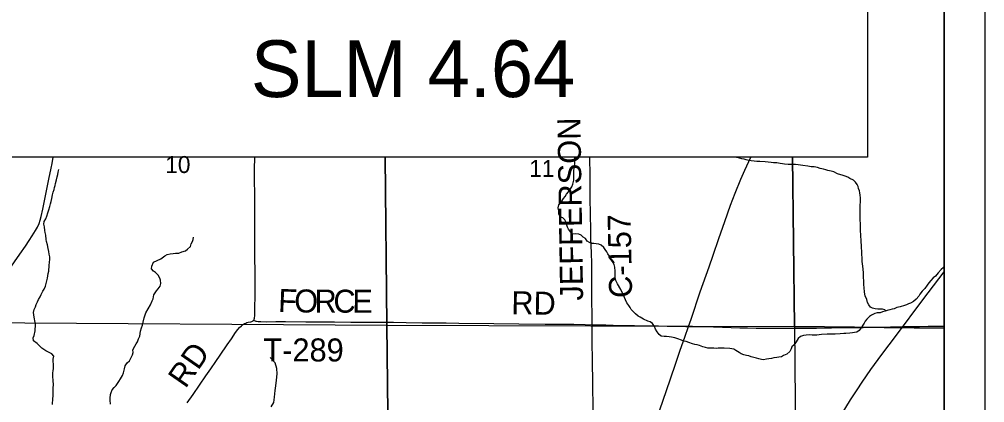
# Model space of a CAD drawing. Extents: x 0 to 34, y 0 to 22.
# Drawn here: x 6.615 to 9, y 16.212 to 17.158 of the extents above; entities that cross this region are included whole.
import ezdxf

# ---------------------------------------------------------------- set-up
doc = ezdxf.new("R2010")
doc.units = 0
for name, color, linetype in [('Default', 7, 'Continuous'), ('GM_X_County_Road', 7, 'Continuous'), ('GM_X_County_Road_Text', 7, 'Continuous'), ('GM_X_Minor_River', 7, 'Continuous'), ('GM_X_Rail_Line', 7, 'Continuous'), ('GM_X_Section', 7, 'Continuous'), ('GM_X_Section_Text', 7, 'Continuous'), ('GM_X_State_Route', 7, 'Continuous'), ('GM_X_Township_Road', 7, 'Continuous'), ('GM_X_Township_Road_Text', 7, 'Continuous'), ('SH_Cut_Line', 7, 'Continuous'), ('SH_Data', 7, 'Continuous'), ('SH_Text', 7, 'Continuous')]:
    doc.layers.add(name, color=color, linetype=linetype)

msp = doc.modelspace()

# ---------------------------------------------------------------- linework, layer by layer
at = {"layer": 'Default'}
msp.add_lwpolyline([(8.9, 14.3696), (8.9, 18.4271)], dxfattribs=at)
for points in [[(8.5252, 16.8178), (8.53, 16.4), (8.9, 16.3958), (8.9, 17.4137), (8.7107, 17.4109), (8.7107, 16.8178)], [(8.9, 15.3782), (8.9, 16.3958), (8.53, 16.4), (8.5395, 15.3753)]]:
    msp.add_lwpolyline(points, close=True, dxfattribs=at)
at = {"layer": 'GM_X_County_Road'}
for points in [[(6.5832, 16.5322), (6.5899, 16.541), (6.6165, 16.579), (6.6299, 16.5987), (6.639, 16.6124), (6.6465, 16.6236), (6.6552, 16.6371), (6.6597, 16.6454), (6.6636, 16.654), (6.6666, 16.6628), (6.669, 16.6719), (6.6729, 16.6901), (6.6802, 16.7268), (6.6874, 16.7635), (6.6934, 16.7906), (6.6959, 16.8026), (6.6988, 16.8178)], [(8.0302, 16.4045), (8.03, 16.4324), (8.0297, 16.4603), (8.0296, 16.4727), (8.0294, 16.4882), (8.0292, 16.5099), (8.0292, 16.5316), (8.029, 16.5564), (8.0283, 16.5813), (8.0271, 16.6185), (8.0268, 16.6341), (8.0266, 16.6434), (8.0265, 16.6524), (8.0263, 16.6628), (8.0261, 16.6741), (8.0255, 16.7205), (8.0253, 16.7452), (8.0249, 16.7793), (8.0247, 16.8104), (8.0247, 16.8178)], [(8.0327, 15.9404), (8.0326, 15.9452), (8.0326, 15.9521), (8.0325, 15.9656), (8.0327, 15.9878), (8.0328, 16.0042), (8.0328, 16.0289), (8.0327, 16.0568), (8.033, 16.0816), (8.0332, 16.1065), (8.0334, 16.122), (8.0336, 16.1406), (8.0336, 16.1592), (8.0335, 16.1716), (8.033, 16.2058), (8.0321, 16.2492), (8.0316, 16.271), (8.0311, 16.3051), (8.0306, 16.3299), (8.0305, 16.3485), (8.0304, 16.3702), (8.0302, 16.4045)]]:
    msp.add_lwpolyline(points, dxfattribs=at)
at = {"layer": 'GM_X_Minor_River'}
for points in [[(8.0398, 16.6046), (8.0345, 16.605), (8.0284, 16.605), (8.0234, 16.6073), (8.0177, 16.6107), (8.0134, 16.6172), (8.0077, 16.621), (8.0027, 16.6259), (7.997, 16.6278), (7.9879, 16.6286), (7.9825, 16.6278), (7.9775, 16.6328), (7.9718, 16.64), (7.9691, 16.6453), (7.9664, 16.6526), (7.9649, 16.6583), (7.963, 16.6636), (7.958, 16.6682), (7.953, 16.6697), (7.948, 16.6784), (7.9476, 16.686), (7.9461, 16.6929), (7.9476, 16.7001), (7.9537, 16.7073), (7.9594, 16.7157), (7.9636, 16.7206), (7.9666, 16.7271), (7.972, 16.7328), (7.9765, 16.74), (7.9799, 16.745), (7.9822, 16.7514), (7.9845, 16.7609), (7.9845, 16.775), (7.9852, 16.7849), (7.986, 16.7902), (7.9867, 16.7951), (7.9871, 16.8035), (7.9871, 16.8085), (7.987, 16.8161), (7.9865, 16.8178)], [(8.7557, 16.4386), (8.7531, 16.4415), (8.7473, 16.443), (8.7359, 16.443), (8.729, 16.4434), (8.7225, 16.4457), (8.7176, 16.4479), (8.7137, 16.4536), (8.7107, 16.4597), (8.7084, 16.4666), (8.7049, 16.4761), (8.7034, 16.4852), (8.7022, 16.4966), (8.7018, 16.5031), (8.7014, 16.5111), (8.7006, 16.5225), (8.7002, 16.5335), (8.699, 16.5491), (8.6975, 16.5605), (8.697, 16.5704), (8.6967, 16.5769), (8.6966, 16.5875), (8.6959, 16.5928), (8.6958, 16.5982), (8.695, 16.6111), (8.6942, 16.6255), (8.6935, 16.6369), (8.6934, 16.6544), (8.6926, 16.6628), (8.6926, 16.6715), (8.6922, 16.6814), (8.6922, 16.6902), (8.6926, 16.6997), (8.6929, 16.7077), (8.6929, 16.7179), (8.6925, 16.7244), (8.6917, 16.7301), (8.6909, 16.735), (8.6886, 16.7404), (8.6871, 16.7453), (8.6848, 16.7506), (8.681, 16.7564), (8.676, 16.7609), (8.6672, 16.7651), (8.6619, 16.7685), (8.6554, 16.7708), (8.65, 16.7731), (8.6367, 16.7773), (8.6275, 16.7815), (8.6206, 16.7834), (8.6126, 16.7853), (8.6076, 16.7864), (8.6019, 16.7883), (8.5931, 16.7902), (8.5866, 16.7925), (8.5786, 16.7941), (8.571, 16.7944), (8.563, 16.796), (8.5504, 16.7975), (8.5389, 16.799), (8.5328, 16.7998), (8.5141, 16.7998), (8.5053, 16.8009), (8.5004, 16.8013), (8.4946, 16.8028), (8.4862, 16.8044), (8.4786, 16.8044), (8.4725, 16.8048), (8.4652, 16.8055), (8.4576, 16.8063), (8.4446, 16.8071), (8.4374, 16.8074), (8.4301, 16.8078), (8.4232, 16.8086), (8.4171, 16.8097), (8.4107, 16.8113), (8.4057, 16.8128), (8.3996, 16.8143), (8.3942, 16.8158), (8.3874, 16.8174), (8.386, 16.8178)], [(6.6785, 16.632), (6.6781, 16.6369), (6.6769, 16.6461), (6.6754, 16.6525), (6.6761, 16.659), (6.6807, 16.6662), (6.6829, 16.6723), (6.6856, 16.6803), (6.6879, 16.6883), (6.6901, 16.6966), (6.6917, 16.7027), (6.6935, 16.7084), (6.6954, 16.7164), (6.6969, 16.7248), (6.6988, 16.732), (6.7007, 16.7381), (6.7019, 16.7434), (6.7038, 16.7483), (6.7045, 16.7533), (6.7068, 16.7624), (6.7087, 16.7693), (6.7102, 16.775), (6.7109, 16.781), (6.7121, 16.7875)], [(6.697, 16.208), (6.6977, 16.2225), (6.6985, 16.2285), (6.6985, 16.2346), (6.6981, 16.2415), (6.6984, 16.2472), (6.6992, 16.2578), (6.6984, 16.265), (6.698, 16.2784), (6.698, 16.286), (6.6983, 16.2909), (6.6991, 16.2966), (6.6994, 16.308), (6.6983, 16.3133), (6.6986, 16.3194), (6.7002, 16.3266), (6.6952, 16.3327), (6.6856, 16.3377), (6.6807, 16.34), (6.6707, 16.3468), (6.6592, 16.3582), (6.6501, 16.3647), (6.6489, 16.3719), (6.6512, 16.378), (6.6542, 16.3898), (6.6546, 16.405), (6.6538, 16.4099), (6.6518, 16.4233), (6.6507, 16.4293), (6.6495, 16.435), (6.6518, 16.4419), (6.6552, 16.4491), (6.6564, 16.4544), (6.6598, 16.4613), (6.6624, 16.4666), (6.6662, 16.4731), (6.6685, 16.4791), (6.6731, 16.4871), (6.6765, 16.4921), (6.6795, 16.4997), (6.6829, 16.5126), (6.6844, 16.5191), (6.6852, 16.5251), (6.6863, 16.5312), (6.6875, 16.5369), (6.6889, 16.551), (6.6897, 16.5586), (6.6901, 16.5655), (6.69, 16.5719), (6.6889, 16.5791), (6.6877, 16.5852), (6.6858, 16.5928), (6.6846, 16.6016), (6.6823, 16.6096), (6.6812, 16.6149), (6.68, 16.6259), (6.6785, 16.632)], [(6.8401, 16.2087), (6.8393, 16.2186), (6.8393, 16.2235), (6.8404, 16.2323), (6.842, 16.2376), (6.8442, 16.2437), (6.8488, 16.2494), (6.8541, 16.2547), (6.861, 16.2642), (6.8652, 16.271), (6.8697, 16.2794), (6.872, 16.2862), (6.875, 16.2961), (6.8765, 16.3033), (6.8811, 16.3106), (6.8868, 16.3155), (6.8902, 16.3224), (6.8944, 16.33), (6.8959, 16.3364), (6.8955, 16.3429), (6.9005, 16.352), (6.9039, 16.3573), (6.9065, 16.3623), (6.9092, 16.3699), (6.9122, 16.3767), (6.9141, 16.3885), (6.9168, 16.3972), (6.919, 16.4033), (6.9205, 16.4109), (6.9236, 16.4212), (6.9277, 16.4337), (6.9334, 16.444), (6.9388, 16.4535), (6.9429, 16.4634), (6.9452, 16.4683), (6.946, 16.4737), (6.9471, 16.4786), (6.9536, 16.4881), (6.9578, 16.4934), (6.9631, 16.4999), (6.9646, 16.5067), (6.9634, 16.5143), (6.9623, 16.5197), (6.9577, 16.5269), (6.9516, 16.5334), (6.9466, 16.5364), (6.9416, 16.5425), (6.9424, 16.5493), (6.9465, 16.5588), (6.9553, 16.5634), (6.9645, 16.5672), (6.974, 16.5748), (6.9805, 16.5782), (6.9873, 16.5797), (6.9953, 16.5805), (7.0007, 16.5809), (7.0087, 16.5812), (7.0167, 16.5843), (7.0251, 16.5869), (7.03, 16.5907), (7.0377, 16.598), (7.0396, 16.604), (7.043, 16.6101), (7.0441, 16.6151), (7.0452, 16.6204)], [(8.6433, 16.3822), (8.6307, 16.3814), (8.6196, 16.3815), (8.6109, 16.3811), (8.5964, 16.3803), (8.5853, 16.3792), (8.5738, 16.3792), (8.5662, 16.3796), (8.5586, 16.3788), (8.5521, 16.3781), (8.5452, 16.3758), (8.5395, 16.3705), (8.5338, 16.3625), (8.5292, 16.3549), (8.5239, 16.3499), (8.5216, 16.345), (8.5182, 16.3389), (8.511, 16.3321), (8.503, 16.3283), (8.4976, 16.3252), (8.4915, 16.3249), (8.4862, 16.3237), (8.479, 16.3226), (8.4732, 16.3215), (8.4667, 16.3203), (8.4606, 16.3192), (8.4538, 16.318), (8.4488, 16.3188), (8.4416, 16.3207), (8.4362, 16.3222), (8.4297, 16.3238), (8.4232, 16.3257), (8.4171, 16.3276), (8.4114, 16.3283), (8.4045, 16.3299), (8.3984, 16.3329), (8.3931, 16.336), (8.3854, 16.3409), (8.3801, 16.3443), (8.3705, 16.3458), (8.356, 16.347), (8.3491, 16.3466), (8.3415, 16.347), (8.3365, 16.3462), (8.3308, 16.3466), (8.3236, 16.3466), (8.3159, 16.347), (8.3102, 16.3482), (8.3033, 16.3497), (8.2957, 16.3535), (8.2896, 16.3546), (8.2839, 16.3562), (8.2778, 16.3573), (8.2694, 16.3604), (8.2621, 16.363), (8.2567, 16.3642), (8.251, 16.3664), (8.2419, 16.3695), (8.2342, 16.3725), (8.2266, 16.3737), (8.2201, 16.3748), (8.2136, 16.3752), (8.2079, 16.3752), (8.201, 16.3767), (8.196, 16.3805), (8.1907, 16.387), (8.1868, 16.3939), (8.1842, 16.3999), (8.1796, 16.4079), (8.1734, 16.4114), (8.1681, 16.4136), (8.1574, 16.4186), (8.149, 16.4232), (8.144, 16.4258), (8.1375, 16.4315), (8.1318, 16.4372), (8.1264, 16.4418), (8.1237, 16.4468), (8.1207, 16.4517), (8.1161, 16.4589), (8.1123, 16.4658), (8.1077, 16.4776), (8.1007, 16.4916), (8.0931, 16.5053), (8.0889, 16.5137), (8.0873, 16.5198), (8.0873, 16.5247), (8.0869, 16.5308), (8.0869, 16.5365), (8.0861, 16.5468), (8.0842, 16.5529), (8.0815, 16.559), (8.0784, 16.5639), (8.0731, 16.5738), (8.0689, 16.5795), (8.0662, 16.5848), (8.0627, 16.5898), (8.0589, 16.5955), (8.0524, 16.6008), (8.0467, 16.6035), (8.0398, 16.6046)], [(8.9, 16.5465), (8.8982, 16.5456), (8.8925, 16.5406), (8.8853, 16.5326), (8.8788, 16.5247), (8.8731, 16.5201), (8.867, 16.5136), (8.8617, 16.5076), (8.8575, 16.5026), (8.8518, 16.4943), (8.8457, 16.4874), (8.8396, 16.4798), (8.8369, 16.4749), (8.8309, 16.4677), (8.824, 16.4623), (8.8171, 16.4578), (8.8118, 16.4559), (8.8068, 16.4536), (8.8015, 16.4517), (8.7908, 16.4487), (8.7832, 16.4471), (8.776, 16.4441), (8.771, 16.4426), (8.7657, 16.4415), (8.7588, 16.4396), (8.7538, 16.438), (8.7477, 16.4365), (8.7416, 16.4342), (8.734, 16.4339), (8.7287, 16.432), (8.7207, 16.4282), (8.7157, 16.4251), (8.7085, 16.4187), (8.705, 16.4133), (8.702, 16.4084), (8.6993, 16.4035), (8.6948, 16.397), (8.6898, 16.3905), (8.6845, 16.386), (8.6784, 16.3856), (8.6731, 16.3848), (8.6666, 16.3841), (8.657, 16.3833), (8.6521, 16.3826), (8.6433, 16.3822)], [(7.2371, 16.2018), (7.2435, 16.2129), (7.2454, 16.2258), (7.2472, 16.2421), (7.2487, 16.2535), (7.2501, 16.2675), (7.2516, 16.2835), (7.2508, 16.2964), (7.2466, 16.3108), (7.2344, 16.324)]]:
    msp.add_lwpolyline(points, dxfattribs=at)
at = {"layer": 'GM_X_Rail_Line'}
msp.add_lwpolyline([(8.645, 16.1818), (8.6683, 16.2192), (8.6849, 16.2441), (8.6974, 16.2625), (8.7191, 16.2938), (8.7461, 16.3308), (8.7822, 16.3791), (8.8472, 16.4656), (8.9, 16.5352)], dxfattribs=at)
at = {"layer": 'GM_X_Section'}
for points in [[(6.4977, 16.8178), (6.4997, 16.4098), (7.5226, 16.4031), (7.5185, 16.8178)], [(7.5185, 16.8178), (7.5226, 16.4031), (8.53, 16.4), (8.5252, 16.8178)], [(6.4997, 16.4098), (7.5226, 16.4031), (7.534, 15.3931), (6.508, 15.3973)], [(7.5226, 16.4031), (8.53, 16.4), (8.5395, 15.3753), (7.534, 15.3931)]]:
    msp.add_lwpolyline(points, close=True, dxfattribs=at)
at = {"layer": 'GM_X_State_Route'}
msp.add_lwpolyline([(8.1514, 16.0603), (8.1616, 16.092), (8.1778, 16.139), (8.188, 16.1684), (8.2227, 16.2682), (8.2377, 16.3123), (8.2479, 16.3417), (8.2589, 16.374), (8.2683, 16.4005), (8.2744, 16.418), (8.2974, 16.4857), (8.319, 16.5475), (8.3292, 16.5761), (8.3434, 16.6176), (8.3577, 16.6595), (8.3721, 16.7), (8.3832, 16.729), (8.3974, 16.7635), (8.4073, 16.7863), (8.4221, 16.8178)], dxfattribs=at)
at = {"layer": 'GM_X_Township_Road'}
for points in [[(7.1936, 16.4151), (7.1941, 16.4157), (7.1948, 16.4169), (7.1954, 16.4181), (7.196, 16.4209), (7.1965, 16.427), (7.1971, 16.4487), (7.1973, 16.4736), (7.1972, 16.5139), (7.1966, 16.5916), (7.1967, 16.6475), (7.1968, 16.694), (7.1965, 16.7282), (7.1963, 16.7593), (7.1963, 16.7872), (7.1964, 16.8178)], [(7.0297, 16.2118), (7.044, 16.2321), (7.0754, 16.2782), (7.0878, 16.2961), (7.1002, 16.3138), (7.1109, 16.3291), (7.1283, 16.3547), (7.1388, 16.37), (7.1491, 16.3856), (7.1547, 16.3932), (7.1589, 16.3978), (7.1636, 16.4021), (7.1661, 16.4041), (7.1687, 16.4058), (7.1714, 16.4074), (7.1743, 16.4087), (7.1773, 16.4098), (7.1804, 16.4106), (7.1866, 16.4118), (7.1894, 16.4126), (7.1909, 16.4131), (7.192, 16.4138), (7.1936, 16.4151)], [(7.1936, 16.4151), (7.1976, 16.4138), (7.1992, 16.4133), (7.2009, 16.4131), (7.205, 16.4128), (7.2115, 16.4124), (7.2252, 16.4121), (7.249, 16.4123), (7.2723, 16.4123), (7.3224, 16.4119), (7.3565, 16.4117), (7.3937, 16.4114), (7.434, 16.411), (7.4681, 16.411), (7.5083, 16.4108), (7.5393, 16.4106), (7.5703, 16.4102), (7.6105, 16.4094), (7.6694, 16.4089), (7.7004, 16.4086), (7.7869, 16.4077), (7.8489, 16.4071), (7.9139, 16.4063), (7.9849, 16.4058), (8.0128, 16.4051), (8.0302, 16.4045)], [(8.0302, 16.4045), (8.0358, 16.4044), (8.0482, 16.4042), (8.0637, 16.4041), (8.0823, 16.4036), (8.107, 16.403), (8.1349, 16.4025), (8.1658, 16.4022), (8.1938, 16.4016), (8.2155, 16.4012), (8.262, 16.4006), (8.2683, 16.4005)], [(8.2683, 16.4005), (8.2837, 16.4003), (8.3085, 16.3998), (8.3954, 16.3973), (8.414, 16.3968), (8.4357, 16.3964), (8.4512, 16.396), (8.4667, 16.3958), (8.4822, 16.3957), (8.5163, 16.3959), (8.538, 16.3961), (8.5845, 16.3964), (8.659, 16.3974), (8.6994, 16.398), (8.7304, 16.3984), (8.7676, 16.3992), (8.7986, 16.3998), (8.8048, 16.4), (8.8264, 16.4004), (8.8388, 16.4005), (8.8605, 16.4008), (8.8884, 16.401), (8.9, 16.4011)]]:
    msp.add_lwpolyline(points, dxfattribs=at)
at = {"layer": 'SH_Cut_Line'}
msp.add_lwpolyline([(8.9, 14.3696), (8.9, 20.9)], dxfattribs=at)
at = {"layer": 'SH_Data'}
for p, q in [((9, 21), (9, 14)), ((8.9, 20.9), (8.9, 14.1))]:
    msp.add_line(p, q, dxfattribs=at)
at = {"layer": 'SH_Text'}
msp.add_lwpolyline([(6.4908, 17.5349), (8.7107, 17.5349), (8.7107, 16.8178), (6.4908, 16.8178)], close=True, dxfattribs=at)

# ---------------------------------------------------------------- texts
at = {"layer": 'GM_X_County_Road_Text'}
for s, rotation, p in [('JEFFERSON', 90.8849, (8.008, 16.4645)), ('C-157', 91.1072, (8.1291, 16.4712))]:
    msp.add_text(s, height=0.05682, rotation=rotation, dxfattribs=at).set_placement(p)
at = {"layer": 'GM_X_Section_Text'}
for s, p in [('10', (6.9754, 16.7789)), ('11', (7.8746, 16.7693))]:
    msp.add_text(s, height=0.04186, rotation=0, dxfattribs=at).set_placement(p)
at = {"layer": 'GM_X_Township_Road_Text'}
for s, height, rotation, p in [('F', 0.0568, 357.7258, (7.2536, 16.4365)), ('O', 0.0568, 359.6771, (7.294, 16.4349)), ('R', 0.0568, 359.7717, (7.3441, 16.4346)), ('C', 0.0568, 359.7717, (7.3908, 16.4344)), ('E', 0.0568, 359.7727, (7.4375, 16.4342)), ('RD', 0.05682, 359.0181, (7.83, 16.4307)), ('T-289', 0.05682, 0, (7.2179, 16.3139)), ('RD', 0.05682, 55.2104, (7.0253, 16.2452))]:
    msp.add_text(s, height=height, rotation=rotation, dxfattribs=at).set_placement(p)
at = {"layer": 'SH_Text'}
msp.add_text('SLM 4.64', height=0.14, dxfattribs=at).set_placement((7.187, 16.9663))

doc.saveas('drawing.dxf')
